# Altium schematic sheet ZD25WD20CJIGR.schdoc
size 127 x 101 mm
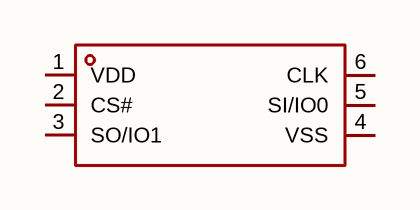
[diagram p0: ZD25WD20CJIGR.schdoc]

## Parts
U?  zd25wd20cjigr  [TSNP-6_L1.0-W0.7-P0.35-BL]  (value not drawn)

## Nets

Not connected (* = marked no-connect by the designer): U? 1(VDD) 2(CS#) 3(SO/IO1) 4(VSS) 5(SI/IO0) 6(CLK)

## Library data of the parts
U? = zd25wd20cjigr: 接口类型:SPI;存储容量:2Mbit;时钟频率(fc):104MHz;; Manufacturer: Zetta(澜智); AddInBom: yes; ModelId: 9065dfb23447488ab815149e1e4399e1; ModelName: TSNP-6_L1.0-W0.7-H0.4-P0.35-BL; ModelTransform: 38.583,25.5905,0,0,0,0,0.003,-0.006,0; Interface: SPI; Memory Size: 2Mbit; Clock Frequency: 104MHz; Voltage - Supply: 1.65V~3.6V; Standby Supply Current: 0.5uA; Program / Erase Cycles: 100000次; Page Programming Time (Tpp): 2ms; Block Erase Time(tBE): 13ms; Data Retention - TDR (Year): 20年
